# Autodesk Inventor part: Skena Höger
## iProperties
Created: 2001-12
Part Number: Skena Höger
Material: Steel, Mild
Document SubType Name: Modeling
Designer: Tobben
Control State: 0
Master: False
Checked Out: False
Shininess: 64.0
Length Units: 11269
Angle Units: 11279
Time Units: 11290
Mass Units: 11283
Length Display Precision: 3
Angle Display Precision: 2
Density: 0.0
Volumn: 0.0
Area: 0.0
PropertySet Name: Model Information
Author: Tobben
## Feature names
1. Derived Body1 [Tagging]
